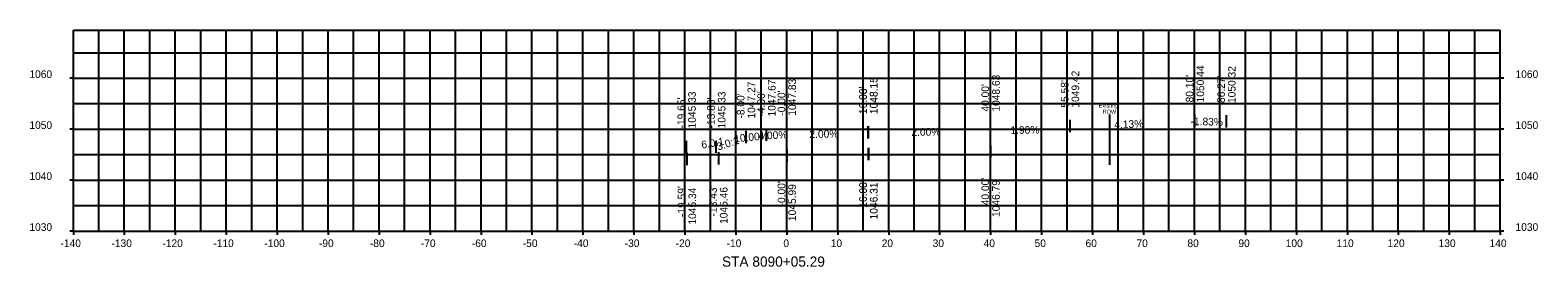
# Model space of a CAD drawing. Extents: x -148 to 147, y 1023 to 1069.
import ezdxf

# ---------------------------------------------------------------- set-up
doc = ezdxf.new("R2010")
doc.units = 0
for name, color, linetype in [('Draft_3', 7, 'Continuous'), ('Draft_4', 7, 'Continuous'), ('Draft_5', 7, 'Continuous'), ('Draft_7', 7, 'Continuous'), ('EXT_SNP', 7, 'Continuous'), ('TL_GroundIntercept', 7, 'Continuous')]:
    doc.layers.add(name, color=color, linetype=linetype)

msp = doc.modelspace()

# ---------------------------------------------------------------- linework, layer by layer
at = {"layer": 'Draft_4'}
for p, q in [((-140, 1069.42), (140, 1069.42)), ((-140, 1030), (-140, 1069.42)), ((140, 1030), (140, 1069.42)), ((-140, 1030), (140, 1030))]:
    msp.add_line(p, q, dxfattribs=at)
at = {"layer": 'Draft_5'}
for p, q in [((16, 1048.15), (16, 1050.55)), ((16, 1048.15), (16, 1050.55)), ((16.03, 1048.15), (16.03, 1050.55)), ((40, 1048.63), (40, 1051.03)), ((40, 1048.63), (40, 1051.03)), ((40, 1048.63), (40, 1051.03)), ((40, 1048.63), (40, 1051.03)), ((55.58, 1049.42), (55.58, 1051.82)), ((55.58, 1049.42), (55.58, 1051.82)), ((80.1, 1050.44), (80.1, 1052.84)), ((86.27, 1050.32), (86.27, 1052.72)), ((-19.65, 1045.33), (-19.65, 1047.73)), ((-13.83, 1045.33), (-13.83, 1047.73)), ((-8, 1047.27), (-8, 1049.67)), ((-8, 1047.27), (-8, 1049.67)), ((-4, 1047.67), (-4, 1050.07)), ((-4, 1047.67), (-4, 1050.07)), ((0, 1047.83), (0, 1050.23)), ((0, 1047.83), (0, 1050.23)), ((-19.59, 1045.34), (-19.59, 1042.94)), ((-13.43, 1045.46), (-13.43, 1043.06)), ((0, 1045.99), (0, 1043.59)), ((0, 1045.99), (0, 1043.59)), ((16, 1046.31), (16, 1043.91)), ((16, 1046.31), (16, 1043.91)), ((16.03, 1046.31), (16.03, 1043.91)), ((40, 1046.79), (40, 1044.39)), ((40, 1046.79), (40, 1044.39)), ((40, 1046.79), (40, 1044.39)), ((40, 1046.79), (40, 1044.39))]:
    msp.add_line(p, q, dxfattribs=at)
at = {"layer": 'Draft_7'}
for p, q in [((-130, 1030), (-130, 1069.42)), ((-120, 1030), (-120, 1069.42)), ((-110, 1030), (-110, 1069.42)), ((-100, 1030), (-100, 1069.42)), ((-90, 1030), (-90, 1069.42)), ((-80, 1030), (-80, 1069.42)), ((-70, 1030), (-70, 1069.42)), ((-60, 1030), (-60, 1069.42)), ((-50, 1030), (-50, 1069.42)), ((-40, 1030), (-40, 1069.42)), ((-30, 1030), (-30, 1069.42)), ((-20, 1030), (-20, 1069.42)), ((-10, 1030), (-10, 1069.42)), ((0, 1030), (0, 1069.42)), ((10, 1030), (10, 1069.42)), ((20, 1030), (20, 1069.42)), ((30, 1030), (30, 1069.42)), ((40, 1030), (40, 1069.42)), ((50, 1030), (50, 1069.42)), ((60, 1030), (60, 1069.42)), ((70, 1030), (70, 1069.42)), ((80, 1030), (80, 1069.42)), ((90, 1030), (90, 1069.42)), ((100, 1030), (100, 1069.42)), ((110, 1030), (110, 1069.42)), ((120, 1030), (120, 1069.42)), ((130, 1030), (130, 1069.42)), ((-140, 1060), (-140.72, 1060)), ((-140, 1060), (140, 1060)), ((140.72, 1060), (140, 1060)), ((-140, 1050), (-140.72, 1050)), ((-140, 1050), (140, 1050)), ((140.72, 1050), (140, 1050)), ((-140, 1040), (-140.72, 1040)), ((-140, 1040), (140, 1040)), ((140.72, 1040), (140, 1040)), ((-140, 1030), (-140.72, 1030)), ((-140, 1030), (-140, 1029.28)), ((-130, 1030), (-130, 1029.28)), ((-120, 1030), (-120, 1029.28)), ((-110, 1030), (-110, 1029.28)), ((-100, 1030), (-100, 1029.28)), ((-90, 1030), (-90, 1029.28)), ((-80, 1030), (-80, 1029.28)), ((-70, 1030), (-70, 1029.28)), ((-60, 1030), (-60, 1029.28)), ((-50, 1030), (-50, 1029.28)), ((-40, 1030), (-40, 1029.28)), ((-30, 1030), (-30, 1029.28)), ((-20, 1030), (-20, 1029.28)), ((-10, 1030), (-10, 1029.28)), ((0, 1030), (0, 1029.28)), ((10, 1030), (10, 1029.28)), ((20, 1030), (20, 1029.28)), ((30, 1030), (30, 1029.28)), ((40, 1030), (40, 1029.28)), ((50, 1030), (50, 1029.28)), ((60, 1030), (60, 1029.28)), ((70, 1030), (70, 1029.28)), ((80, 1030), (80, 1029.28)), ((90, 1030), (90, 1029.28)), ((100, 1030), (100, 1029.28)), ((110, 1030), (110, 1029.28)), ((120, 1030), (120, 1029.28)), ((130, 1030), (130, 1029.28)), ((140, 1030), (140, 1029.28)), ((140.72, 1030), (140, 1030))]:
    msp.add_line(p, q, dxfattribs=at)
at = {"layer": 'EXT_SNP'}
for p, q in [((-135, 1030), (-135, 1069.42)), ((-125, 1030), (-125, 1069.42)), ((-115, 1030), (-115, 1069.42)), ((-105, 1030), (-105, 1069.42)), ((-95, 1030), (-95, 1069.42)), ((-85, 1030), (-85, 1069.42)), ((-75, 1030), (-75, 1069.42)), ((-65, 1030), (-65, 1069.42)), ((-55, 1030), (-55, 1069.42)), ((-45, 1030), (-45, 1069.42)), ((-35, 1030), (-35, 1069.42)), ((-25, 1030), (-25, 1069.42)), ((-15, 1030), (-15, 1069.42)), ((-5, 1030), (-5, 1069.42)), ((5, 1030), (5, 1069.42)), ((15, 1030), (15, 1069.42)), ((25, 1030), (25, 1069.42)), ((35, 1030), (35, 1069.42)), ((45, 1030), (45, 1069.42)), ((55, 1030), (55, 1069.42)), ((65, 1030), (65, 1069.42)), ((75, 1030), (75, 1069.42)), ((85, 1030), (85, 1069.42)), ((95, 1030), (95, 1069.42)), ((105, 1030), (105, 1069.42)), ((115, 1030), (115, 1069.42)), ((125, 1030), (125, 1069.42)), ((135, 1030), (135, 1069.42)), ((-140, 1065), (140, 1065)), ((-140, 1055), (140, 1055)), ((-140, 1045), (140, 1045)), ((-140, 1035), (140, 1035))]:
    msp.add_line(p, q, dxfattribs=at)
at = {"layer": 'TL_GroundIntercept'}
msp.add_line((63.3, 1052.85), (63.3, 1043.01), dxfattribs=at)

# ---------------------------------------------------------------- texts
at = {"layer": 'Draft_3'}
for s, height, p in [('1060', 1.5, (-148.63, 1060.03)), ('1060', 1.5, (143, 1060.03)), ('1050', 1.5, (-148.63, 1050.03)), ('1050', 1.5, (143, 1050.03)), ('1040', 1.5, (-148.63, 1040.03)), ('1040', 1.5, (143, 1040.03)), ('1030', 1.5, (-148.63, 1030.03)), ('1030', 1.5, (143, 1030.03)), ('-140', 1.5, (-142.53, 1026.85)), ('-130', 1.5, (-132.53, 1026.85)), ('-120', 1.5, (-122.53, 1026.85)), ('-110', 1.5, (-112.53, 1026.85)), ('-100', 1.5, (-102.53, 1026.85)), ('-90', 1.5, (-91.81, 1026.85)), ('-80', 1.5, (-81.81, 1026.85)), ('-70', 1.5, (-71.81, 1026.85)), ('-60', 1.5, (-61.81, 1026.85)), ('-50', 1.5, (-51.81, 1026.85)), ('-40', 1.5, (-41.81, 1026.85)), ('-30', 1.5, (-31.81, 1026.85)), ('-20', 1.5, (-21.81, 1026.85)), ('-10', 1.5, (-11.81, 1026.85)), ('0', 1.5, (-0.67, 1026.85)), ('10', 1.5, (8.62, 1026.85)), ('20', 1.5, (18.62, 1026.85)), ('30', 1.5, (28.62, 1026.85)), ('40', 1.5, (38.62, 1026.85)), ('50', 1.5, (48.62, 1026.85)), ('60', 1.5, (58.62, 1026.85)), ('70', 1.5, (68.62, 1026.85)), ('80', 1.5, (78.62, 1026.85)), ('90', 1.5, (88.62, 1026.85)), ('100', 1.5, (97.9, 1026.85)), ('110', 1.5, (107.9, 1026.85)), ('120', 1.5, (117.9, 1026.85)), ('130', 1.5, (127.9, 1026.85)), ('140', 1.5, (137.9, 1026.85)), ('STA 8090+05.29', 2.004, (-12.71, 1023))]:
    msp.add_text(s, height=height, dxfattribs=at).set_placement(p)
at = {"layer": 'Draft_5'}
for s, rotation, p in [('1050.44', 90, (81.9, 1055.24)), ('1050.32', 90, (88.07, 1055.12)), ('1047.27', 90, (-6.2, 1052.07)), ('1047.27', 90, (-6.2, 1052.07)), ('1047.67', 90, (-2.2, 1052.47)), ('1047.67', 90, (-2.2, 1052.47)), ('1047.83', 90, (1.8, 1052.63)), ('1047.83', 90, (1.8, 1052.63)), ('1048.15', 90, (17.8, 1052.95)), ('1048.15', 90, (17.8, 1052.95)), ('1048.15', 90, (17.83, 1052.95)), ('1048.63', 90, (41.8, 1053.43)), ('1048.63', 90, (41.8, 1053.43)), ('1048.63', 90, (41.8, 1053.43)), ('1048.63', 90, (41.8, 1053.43)), ("55.58'", 90, (55.28, 1054.22)), ("55.58'", 90, (55.28, 1054.22)), ('1049.42', 90, (57.38, 1054.22)), ('1049.42', 90, (57.38, 1054.22)), ("80.10'", 90, (79.8, 1055.24)), ("86.27'", 90, (85.97, 1055.12)), ('1045.33', 90, (-17.85, 1050.13)), ('1045.33', 90, (-12.03, 1050.13)), ("-8.00'", 90, (-8.3, 1052.07)), ("-8.00'", 90, (-8.3, 1052.07)), ("-4.00'", 90, (-4.3, 1052.47)), ("-4.00'", 90, (-4.3, 1052.47)), ("-0.00'", 90, (-0.3, 1052.63)), ("-0.00'", 90, (-0.3, 1052.63)), ("16.00'", 90, (15.7, 1052.95)), ("16.00'", 90, (15.7, 1052.95)), ("16.03'", 90, (15.73, 1052.95)), ("40.00'", 90, (39.7, 1053.43)), ("40.00'", 90, (39.7, 1053.43)), ("40.00'", 90, (39.7, 1053.43)), ("40.00'", 90, (39.7, 1053.43)), ("-19.65'", 90, (-19.95, 1050.13)), ("-13.83'", 90, (-14.13, 1050.13)), ('1.90%', 1.0857, (43.9, 1049.03)), ('4.13%', 2.3637, (64.3, 1050.11)), ('-1.83%', 358.9506, (79.22, 1050.78)), ('6.0:1', 9.4642, (-16.64, 1046.16)), ('3.0:1', 18.4349, (-13.46, 1045.78)), ('10.00%', 5.7106, (-10.24, 1047.37)), ('10.00%', 5.7106, (-10.24, 1047.37)), ('4.00%', 2.2906, (-5.54, 1047.94)), ('4.00%', 2.2906, (-5.54, 1047.94)), ('2.00%', 1.1458, (4.46, 1048.25)), ('2.00%', 1.1458, (4.46, 1048.25)), ('2.00%', 1.1458, (24.46, 1048.65)), ("-19.59'", 90, (-19.89, 1032.74)), ("-13.43'", 90, (-13.73, 1032.86)), ('1045.46', 90, (-11.63, 1031.39)), ("-0.00'", 90, (-0.3, 1034.83)), ("-0.00'", 90, (-0.3, 1034.83)), ('1045.99', 90, (1.8, 1031.95)), ('1045.99', 90, (1.8, 1031.95)), ("16.00'", 90, (15.7, 1034.57)), ("16.00'", 90, (15.7, 1034.57)), ("16.03'", 90, (15.73, 1034.57)), ('1046.31', 90, (17.8, 1032.28)), ('1046.31', 90, (17.8, 1032.28)), ('1046.31', 90, (17.83, 1032.28)), ("40.00'", 90, (39.7, 1035.05)), ("40.00'", 90, (39.7, 1035.05)), ("40.00'", 90, (39.7, 1035.05)), ("40.00'", 90, (39.7, 1035.05)), ('1046.79', 90, (41.8, 1032.75)), ('1046.79', 90, (41.8, 1032.75)), ('1046.79', 90, (41.8, 1032.75)), ('1046.79', 90, (41.8, 1032.75)), ('1045.34', 90, (-17.79, 1031.26))]:
    msp.add_text(s, height=1.5, rotation=rotation, dxfattribs=at).set_placement(p)
at = {"layer": 'TL_GroundIntercept'}
for s, p in [('Existing', (61.21, 1054.2)), ('ROW', (61.98, 1053.02))]:
    msp.add_text(s, height=0.787, dxfattribs=at).set_placement(p)

doc.saveas('drawing.dxf')
